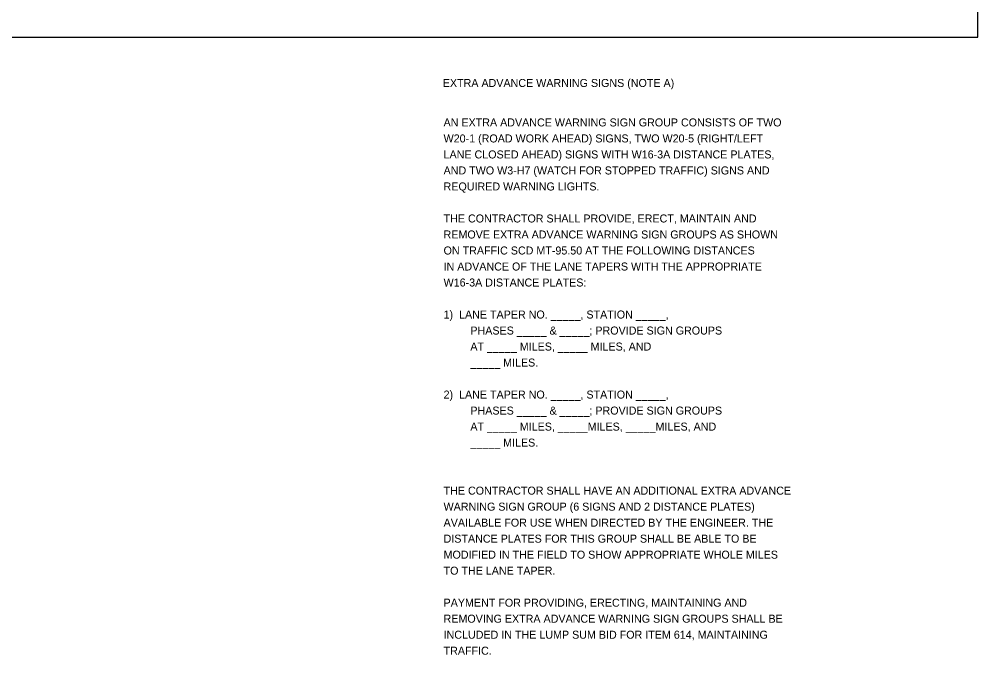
# Model space of a CAD drawing. Extents: x 0 to 34, y -10.8 to 22.
# Drawn here: x 17.24 to 34, y -10.8 to 0.32 of the extents above; entities that cross this region are included whole.
import ezdxf

# ---------------------------------------------------------------- set-up
doc = ezdxf.new("R2010")
doc.units = 0
doc.layers.add('SH_Cut_Line', color=7, linetype='Continuous')
doc.layers.add('SH_Text', color=7, linetype='Continuous')

msp = doc.modelspace()

# ---------------------------------------------------------------- linework, layer by layer
at = {"layer": 'SH_Cut_Line'}
msp.add_lwpolyline([(0, 0), (34, 0), (34, 22), (0, 22)], close=True, dxfattribs=at)

# ---------------------------------------------------------------- texts
at = {"layer": 'SH_Text'}
for s, p in [('EXTRA ADVANCE WARNING SIGNS (NOTE A)', (24.646, -0.87)), ('AN EXTRA ADVANCE WARNING SIGN GROUP CONSISTS OF TWO', (24.66, -1.56)), ('W20-1 (ROAD WORK AHEAD) SIGNS, TWO W20-5 (RIGHT/LEFT', (24.66, -1.84)), ('LANE CLOSED AHEAD) SIGNS WITH W16-3A DISTANCE PLATES,', (24.66, -2.12)), ('AND TWO W3-H7 (WATCH FOR STOPPED TRAFFIC) SIGNS AND', (24.66, -2.4)), ('REQUIRED WARNING LIGHTS.', (24.66, -2.68)), ('THE CONTRACTOR SHALL PROVIDE, ERECT, MAINTAIN AND', (24.66, -3.24)), ('REMOVE EXTRA ADVANCE WARNING SIGN GROUPS AS SHOWN', (24.66, -3.52)), ('ON TRAFFIC SCD MT-95.50 AT THE FOLLOWING DISTANCES', (24.66, -3.8)), ('IN ADVANCE OF THE LANE TAPERS WITH THE APPROPRIATE', (24.66, -4.08)), ('W16-3A DISTANCE PLATES:', (24.66, -4.36)), ('1)  LANE TAPER NO. _____, STATION _____,', (24.66, -4.92)), ('         PHASES _____ & _____; PROVIDE SIGN GROUPS', (24.66, -5.2)), ('         AT _____ MILES, _____ MILES, AND', (24.66, -5.48)), ('         _____ MILES.', (24.66, -5.76)), ('2)  LANE TAPER NO. _____, STATION _____,', (24.66, -6.32)), ('         PHASES _____ & _____; PROVIDE SIGN GROUPS', (24.66, -6.6)), ('         AT _____ MILES, _____MILES, _____MILES, AND', (24.66, -6.88)), ('         _____ MILES.', (24.66, -7.16)), ('THE CONTRACTOR SHALL HAVE AN ADDITIONAL EXTRA ADVANCE', (24.66, -8)), ('WARNING SIGN GROUP (6 SIGNS AND 2 DISTANCE PLATES)', (24.66, -8.28)), ('AVAILABLE FOR USE WHEN DIRECTED BY THE ENGINEER. THE', (24.66, -8.56)), ('DISTANCE PLATES FOR THIS GROUP SHALL BE ABLE TO BE', (24.66, -8.84)), ('MODIFIED IN THE FIELD TO SHOW APPROPRIATE WHOLE MILES', (24.66, -9.12)), ('TO THE LANE TAPER.', (24.66, -9.4)), ('PAYMENT FOR PROVIDING, ERECTING, MAINTAINING AND', (24.66, -9.96)), ('REMOVING EXTRA ADVANCE WARNING SIGN GROUPS SHALL BE', (24.66, -10.24)), ('INCLUDED IN THE LUMP SUM BID FOR ITEM 614, MAINTAINING', (24.66, -10.52)), ('TRAFFIC.', (24.66, -10.8))]:
    msp.add_text(s, height=0.14, dxfattribs=at).set_placement(p)

doc.saveas('drawing.dxf')
